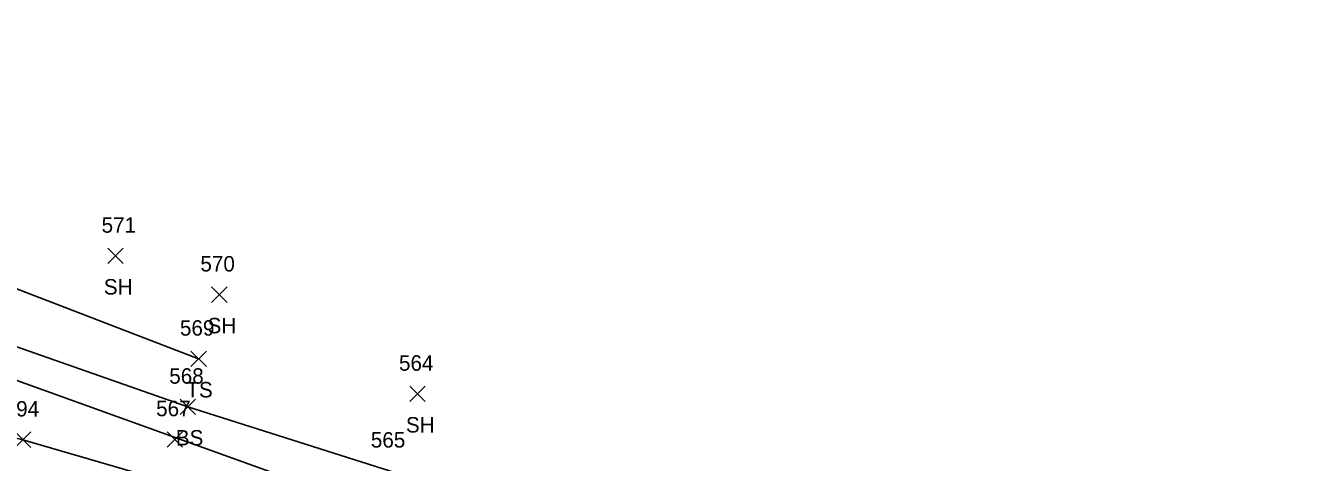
# Model space of a CAD drawing. Extents: x 1678863 to 1683592, y 407783 to 418211.
# Drawn here: x 1681509.2 to 1681675.9, y 417861.7 to 417918.2 of the extents above; entities that cross this region are included whole.
import ezdxf

# ---------------------------------------------------------------- set-up
doc = ezdxf.new("R2010")
doc.units = 0
for name, color, linetype in [('DCP', 7, 'Continuous'), ('L_A', 7, 'Continuous'), ('L_I', 7, 'Continuous'), ('L_TIC', 7, 'Continuous'), ('LAPB', 7, 'Continuous'), ('LELB', 7, 'Continuous')]:
    doc.layers.add(name, color=color, linetype=linetype)

msp = doc.modelspace()

# ---------------------------------------------------------------- linework, layer by layer
at = {"layer": 'DCP'}
msp.add_lwpolyline([(1681578.18, 417847.06), (1681380.6, 417918.23)], dxfattribs=at)
at = {"layer": 'L_TIC'}
for points in [[(1681519.85, 417887.44), (1681521.85, 417889.44)], [(1681521.85, 417887.44), (1681519.85, 417889.44)], [(1681533.29, 417882.42), (1681535.29, 417884.42)], [(1681535.29, 417882.42), (1681533.29, 417884.42)], [(1681530.61, 417874.12), (1681532.61, 417876.12)], [(1681532.61, 417874.12), (1681530.61, 417876.12)], [(1681558.96, 417869.58), (1681560.96, 417871.58)], [(1681560.96, 417869.58), (1681558.96, 417871.58)], [(1681529.21, 417867.9), (1681531.21, 417869.9)], [(1681531.21, 417867.9), (1681529.21, 417869.9)], [(1681507.87, 417863.65), (1681509.87, 417865.65)], [(1681509.87, 417863.65), (1681507.87, 417865.65)], [(1681527.52, 417863.69), (1681529.52, 417865.69)], [(1681529.52, 417863.69), (1681527.52, 417865.69)]]:
    msp.add_lwpolyline(points, dxfattribs=at)
at = {"layer": 'LAPB'}
msp.add_lwpolyline([(1681570.34, 417832.86), (1681571.84, 417844.31), (1681544.03, 417854.39), (1681508.87, 417864.65), (1681488.64, 417869.55), (1681485.17, 417876.69), (1681477.98, 417886.59), (1681460.97, 417893.2), (1681439.79, 417898.34), (1681437.9, 417893.9)], dxfattribs=at)
at = {"layer": 'LELB'}
for points in [[(1681531.61, 417875.12), (1681503.98, 417885.72), (1681481.71, 417894.14), (1681469.9, 417913.75)], [(1681808.38, 417761.41), (1681772.94, 417773.89), (1681739.45, 417784.06), (1681717.85, 417793.04), (1681686.59, 417805.76), (1681670.52, 417813.86), (1681638.93, 417826.92), (1681609.78, 417837.5), (1681593.01, 417844.94), (1681556.32, 417860.63), (1681530.21, 417868.9), (1681501.4, 417878.99), (1681480.67, 417886.23), (1681463.08, 417899.46), (1681453.92, 417912.7)]]:
    msp.add_lwpolyline(points, dxfattribs=at)

# ---------------------------------------------------------------- texts
at = {"layer": 'L_A'}
for s, p in [('SH', (1681519.34, 417883.44)), ('SH', (1681532.77, 417878.42)), ('TS', (1681530.02, 417870.12)), ('SH', (1681558.45, 417865.58)), ('BS', (1681528.66, 417863.9))]:
    msp.add_text(s, height=2, dxfattribs=at).set_placement(p)
at = {"layer": 'L_I'}
for s, p in [('571', (1681519.05, 417891.44)), ('570', (1681531.84, 417886.42)), ('569', (1681529.19, 417878.12)), ('564', (1681557.55, 417873.58)), ('568', (1681527.81, 417871.9)), ('794', (1681506.5, 417867.65)), ('567', (1681526.11, 417867.69)), ('565', (1681553.91, 417863.63)), ('565', (1681553.91, 417863.63))]:
    msp.add_text(s, height=2, dxfattribs=at).set_placement(p)

doc.saveas('drawing.dxf')
